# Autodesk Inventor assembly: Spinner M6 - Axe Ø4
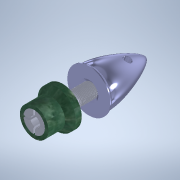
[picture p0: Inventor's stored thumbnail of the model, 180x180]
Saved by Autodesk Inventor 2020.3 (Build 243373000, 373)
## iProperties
Created: 2015-08
Part Number: Spinner M6 - Axe Ø4
Document SubType Name: Assembly
Designer: ficho
Sending System: SolidWorks 2014
Last Author: Guillaume
Last Saved: 2015-08-26
Author: ficho
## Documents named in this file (4)
- G:\travail\année 2019-2020\1sti2d modélisation\Spinner M6 - Axe Ø4.iam
- G:\travail\année 2019-2020\1sti2d modélisation\SPINNER V2 - Axe M6.ipt
- G:\travail\année 2019-2020\1sti2d modélisation\SPINNER V2 - Bloc M6 .ipt
- G:\travail\année 2019-2020\1sti2d modélisation\SPINNER V2 - Tête M6 .ipt
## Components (3 placed, 3 different names)
1. SPINNER V2 - Axe M6:1
2. SPINNER V2 - Bloc M6 :1
3. SPINNER V2 - Tête M6 :1
